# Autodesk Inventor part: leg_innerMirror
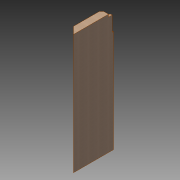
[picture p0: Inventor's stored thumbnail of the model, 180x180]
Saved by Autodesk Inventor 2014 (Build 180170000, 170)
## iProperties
Created: 2014-05
Part Number: leg_innerMirror
Material: Maple
Document SubType Name: Modeling
Designer: t_emanb
Density: 1 g/cm^3
Appearance: Maple - Solid Natural Medium Gloss
Author: t_emanb
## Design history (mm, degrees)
sketch "Sketch1"
  geometry: L1 (0, 0)-(-17.78, 0); L2 (-17.78, 0)-(-17.78, -101.6); L3 (-17.78, -101.6)-(0, -101.6); L4 (0, -101.6)-(0, 0)
  constraints: 8 end point, 2 parallel, 1 horizontal, 1 perpendicular
  dimensions: "d0" = 101.6 distance of L3.end L1.start; "d1" = 17.78 distance of L1.start L1.end
extrude "Extrusion1" new body sketch "Sketch1" distance "d2" = 304.8; taper "d3" = 0 deg
sketch "Sketch2"
  geometry: L1 (0, 0)-(17.78, 0) reference; L2 (17.78, 101.6)-(0, 101.6) reference; L3 (0, 101.6)-(0, 0) reference; L4 (17.78, 101.6)-(0, 83.82); L5 (17.78, 0)-(0, 17.78)
  constraints: 4 end point, 2 point on line
  dimensions: "d4" = 45 deg angle of L1 L5; "d5" = 45 deg angle of L2 L4
extrude "Extrusion2" cut sketch "Sketch2" stored distance "d6" = 304.8; taper "d7" = 0 deg
sketch "Sketch5"
  geometry: L1 (17.78, 0)-(17.78, 101.6) reference; L2 (17.78, 101.6)-(0, 83.82) reference; L3 (5.08, 88.9)-(17.78, 88.9); 1 further point
  constraints: 2 end point, 2 point on line, 1 perpendicular
  dimensions: "d14" = 88.9 distance from line of point (0, 0) L3
extrude "Extrusion5" cut sketch "Sketch5" distance "d15" = 6.35; taper "d16" = 0 deg
sketch "Sketch4"
  geometry: L1 (17.78, 0)-(17.78, 101.6) reference; L2 (0, 83.82)-(0, 17.78) reference; L3 (17.78, 98.425)-(14.605, 98.425); L4 (17.78, 101.6)-(0, 83.82) reference; 1 further point
  constraints: 2 end point, 2 point on line, 1 perpendicular
  dimensions: "d11" = 98.425 distance from line of point (0, 0) L3
extrude "Extrusion4" cut sketch "Sketch4" distance "d12" = 44.45; taper "d13" = 0 deg
body "Solid1"
